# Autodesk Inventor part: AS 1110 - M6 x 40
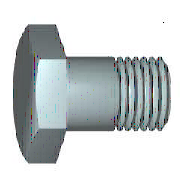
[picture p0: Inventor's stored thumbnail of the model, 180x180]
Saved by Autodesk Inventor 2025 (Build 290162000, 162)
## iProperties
Created: 2024-01
Part Number: AS 1110 - M6 x 40
Material: Acciaio, Dolce
Description: Bulloni e viti di precisione esagonali metrici ISO
Document SubType Name: Modeling
Standard: AS 1110
Designer: R5800u
Standards Organization: AS
Language: it-IT
Size Designation: M6 x 40
Categories: <MemberInstance><Categories><Category DisplayName="Elementi di fissaggio" InternalName="e4da775c-781d-43d5-af7c-5136215cf5a6" Mnemonic="FSTN"><Category DisplayN
Density: 7.85 g/cm^3
Appearance: Semilucidato
IsCustomPart: 0
Author: R5800u
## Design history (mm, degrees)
body "Solid1"
workplane "Work Plane1"
revolve "Corpo" stored, may be unused: angle "d12" = 90 deg
sketch "Schizzo2"
  geometry: L1 (0, 5.774)-(5, 2.887); L2 (5, 2.887)-(5, -2.887); L3 (5, -2.887)-(0, -5.774); L4 (0, -5.774)-(-5, -2.887); L5 (-5, -2.887)-(-5, 2.887); L6 (-5, 2.887)-(0, 5.774); 2 further points
  constraints: 12 end point, 1 coincident, 1 vertical, 11 other
  dimensions: "d11" = 10 distance between parallel lines of L5 L2 (= SW)
extrude "Testa" join sketch "Schizzo2" distance "d3" = 3.5 (= KOH - SD); taper "d4" = 0 deg
revolve "Smusso1" stored, may be unused: angle "d21" = 90 deg
feature "Filettatura" dims "d15" = 37 (= GEL), "d16" = 0
chamfer "Smusso2" distance "d6" = 0.61345 (= -0.5 x SPD + 0.5 x GD); stored, may be unused: second distance "d7" = 0.61355 (computed from GUL), angle "d55" = 45 deg
sketch "Schizzo1"
  geometry: L1 (0, 5)-(0, 3); L2 (3, 3)-(40, 3); L3 (40, 3)-(40, 0); L4 (40, 0)-(-0.5, 0); L5 (-8.6, 0)-(48.1, 0) reference; L6 (-0.5, 0)-(-0.5, 5); L7 (-0.5, 5)-(0, 5); L8 (3, 3)-(2.386, 3); L9 (2.386, 3)-(0, 3); L10 (0, -1)-(0, 6) reference
  constraints: 16 end point, 2 collinear, 2 perpendicular, 1 parallel
  dimensions: "d0" = 40 distance between parallel lines of L3 L1 (= NLG); "d1" = 37 distance from line of L2.start L3 (= GEL); "d2" = 6 diameter of L2 L4 (= GD); "d9" = 0.5001 distance between parallel lines of L6 L1 (computed from SD); "d10" = 10 diameter of L7 L4 (= SD2); "d13" = 0.61355 distance of L2.start L8.end (computed from GAL); "d14" = 6 diameter of L9 L4 (= BDM)
sketch "Schizzo4"
  geometry: L1 (-4, 5)-(-4, 5.774); L2 (-4, 5.774)-(-3.554, 5.774); L3 (-3.554, 5.774)-(-4, 5); L4 (-4.7, 0)-(0.2, 0) reference; L5 (-0.5, 5.774)-(-4, 5.774) reference; L6 (-4, 2.887)-(-4, 5.774) reference
  constraints: 6 end point, 2 collinear, 1 perpendicular, 1 vertical
  dimensions: "d5" = 30 deg angle of L3 L1 (= ANG1); "d19" = 10 diameter of L1.start L4 (= SW0)
other parameters: "NLG" = 40 [user parameter; used in 1 equation term], "GD" = 6 (= NND) [user parameter; used in 2 equation terms], "BDM" = 6 (= NND) [user parameter; used in 1 equation term], "KOH" = 4 [user parameter; used in 1 equation term], "GEL" = 37 [user parameter; used in 2 equation terms], "SW" = 10 [user parameter; used in 5 equation terms], "SW0" = 10 (= SW) [user parameter; used in 1 equation term], "SPD" = 4.7731 (= NND - 1.2269 x PTC) [user parameter; used in 1 equation term], "SD2" = 10 (= SW) [user parameter; used in 1 equation term], "SD" = 0.5 [user parameter; used in 3 equation terms], "ANG1" = 30 deg [user parameter; used in 1 equation term], "GAL" = 0.61345 (= 0.61345 x PTC) [user parameter; used in 1 equation term], "GUL" = 0.61345 (= 0.61345 x PTC) [user parameter; used in 1 equation term], "d8" = 0, "RR" = 0.25 [user parameter], "d57" = 0, "d58" = 0, "WFT" = 0.5 (= SD) [user parameter], "GD1" = 4.7731 (= THREADDIA - 1.2269 x PTC) [user parameter], "THREADDIA" = 6 [user parameter; used in 1 equation term], "TOA" = 30 deg [user parameter], "FAWI" = 45 deg [user parameter], "PTC" = 1 [user parameter; used in 5 equation terms], "NND" = 6 [user parameter; used in 3 equation terms], "E0" = 11.55 (= 1.155 x SW) [user parameter]
